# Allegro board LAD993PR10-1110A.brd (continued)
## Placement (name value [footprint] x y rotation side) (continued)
DE8  AZ5125-01H.R7G_SOD523-2  [AZ5125-01HPR7G_SOD523-2]  238.4 31.36 0 top
DE9  -  [RB751S40T1G_SOD523-2]  244.55 38.09 180 top
DH1  -  [RB751S40T1G_SOD523-2]  168.28 20.75 90 top
DI1  -  [RB751S40T1G_SOD523-2]  63.96 27.93 180 top
DI3  AZ5125-02S.R7G_SOT23-3  [AZ5125-02SPR7G_SOT23-3]  62.09 17.9 90 bottom
DI7  -  [AZ1045-04F_DFN2510P10E-10-9]  293.06 53.19 270 bottom
DI8  AZ5125-02S.R7G_SOT23-3  [AZ5125-02SPR7G_SOT23-3]  290.69 56.89 90 bottom
DI9  -  [AZ1045-04F_DFN2510P10E-10-9]  291.91 34.14 270 bottom
DI10  AZ5125-02S.R7G_SOT23-3  [AZ5125-02SPR7G_SOT23-3]  290.18 36.82 90 bottom
DN1  -  [RB751S40T1G_SOD523-2]  197.37 36.38 270 bottom
DN2  -  [RB751S40T1G_SOD523-2]  196.22 36.38 270 bottom
DV1  -  [RB751S40T1G_SOD523-2]  176.47 14.06 180 top
DV2  BAT54CW-7-F_SOT323-3~D  [BAT54CW-7-F_SOT323-3]  65.4 31.46 90 top
DV3  BAT54CW-7-F_SOT323-3~D  [BAT54CW-7-F_SOT323-3]  65.35 33.9 90 top
DV4  -  [AZ1045-04F_DFN2510P10E-10-9]  296.54 78.15 180 top
DV5  -  [AZ1045-04F_DFN2510P10E-10-9]  292.32 66.61 0 top
DV9  -  [RB751S40T1G_SOD523-2]  174.63 71.49 90 bottom
DV11  -  [RB751S40T1G_SOD523-2]  173.75 74.41 90 top
DV12  -  [PESD5V0U2BT_SOT23-3]  233.96 36.91 90 bottom
DV13  -  [BAT54CW-7-F_SOT323-3]  170.19 72.78 90 top
DV14  -  [BAT54CW-7-F_SOT323-3]  150.19 110.53 0 top
DZ1  -  [RB751S40T1G_SOD523-2]  150.39 18.44 0 top
DZ2  -  [RB751S40T1G_SOD523-2]  63.35 63.46 180 top
EC5205  6.8P_0402_50V8C  [C_0402]  240.67 36.77 270 bottom
EC5206  6.8P_0402_50V8C  [C_0402]  241.69 36.77 270 bottom
F1  0.5A_13.2V_NANOSMDC050F-13.2-2  [F_NANOSMDC050F-13P2-2]  122.96 14.32 0 top
FD1  FIDUCAL  [FIDUCIAL_C40M80]  296.58 121.01 180 bottom
FD2  FIDUCIAL  [FIDUCIAL_C40M80]  15.54 13.13 0 top
FD3  FIDUCAL  [FIDUCIAL_C40M80]  6.55 17.16 180 bottom
FD4  FIDUCIAL  [FIDUCIAL_C40M80]  293.28 121.05 0 top
H1  -  [H_3P7]  80.49 108.8 0 top
H2  -  [H_3P7]  139.79 104.55 0 top
H3  -  [H_3P7]  80.49 70.4 0 top
H4  -  [H_3P7]  139.79 71 0 top
H5  -  [H_3P2]  196.29 114.15 0 top
H6  -  [H_3P2]  210.69 68.55 0 top
H10  -  [H_2P8]  85.19 128.9 0 top
H11  -  [H_2P8]  194.09 128.9 0 top
H12  -  [H_2P8]  285.89 107.9 0 top
H13  -  [H_2P5]  304.79 119.2 0 top
H17  -  [H_2P8]  65.29 76.9 0 top
H19  -  [H_2P8]  214.14 53.1 0 top
H20  -  [H_3P3]  40.79 41.75 0 top
H23  -  [H_2P5]  57.49 57.4 0 top
H40  -  [H_2P1N]  301.29 41 0 top
H55  -  [H_2P4X2P1N]  15.29 41 0 top
H56  -  [H_2P5]  88.64 6.97 0 top
H57  -  [H_3P0]  88.64 8.57 0 top
HDA1  ALC3246-CG-GP  [ALC3246-CG_MQFN48_6X6-S]  278.26 26.95 0 top
HT1  100K +-1% 0402 B25/50 4250K  [R_0402]  108.39 85.72 0 top
JADP10  ACES_50290-00701-001  [ACES_50290-00701-001_7P]  8.94 30.4 90 bottom
JAPS  ACES_50506-01841-P01  [ACES_50506-01841-P01_18P]  173.18 11.55 0 top
JBAT10  ACES_50288-01171-001  [ACES_50288-01171-001_11P-T]  45.19 10.84 180 bottom
JBL1  E-T_6913K-Y04N-00L  [E-T_6913K-Y04N-00L_4P]  121.59 15.83 180 bottom
JCAM1  ACES_87212-14G0  [ACES_87212-14G0_14P]  241.02 43.51 0 bottom
JDEG1  ACES_50506-01041-P01  [ACES_50506-01041-P01_10P]  249.22 34.41 0 bottom
JDIMM1  DEREN_40-42271-26001RHF  [DEREN_40-42271-26001RHF_260P-T]  70.65 40.97 0 bottom
JDIMM2  LOTES_ADDR0070-P009A  [LOTES_ADDR0070-P009A_260P-T]  70.66 28.17 180 bottom
JEDP1  ACES_59003-04006-001  [ACES_59003-04006-001_40P]  62.69 24.01 270 bottom
JFAN1  E-T_3806K-F04N-03R  [E-T_3806K-F04N-03R_4P]  56.51 34.65 180 top
JFAN2  E-T_3806K-F04N-03R  [E-T_3806K-F04N-03R_4P]  246.94 34.43 90 top
JHDD1  ACES_50554-01201-001  [ACES_50554-01201-001_12P-T]  195.67 12.21 180 bottom
JHDMI1  ACON_HMR2E-AK120D  [ACON_HMR2E-AK120D_19P]  301.86 78.17 270 bottom
JHP1  SINGA_2SJ3108-007111F  [SINGA_2SJ3108-007111F_6P]  300.84 18.12 90 bottom
JIO1  ACES_88194-3041  [ACES_88194-3041_30P]  9.9 22.75 270 top
JKB1  ACES_50699-03041-P01  [ACES_50699-03041-P01_30P]  196.93 56.91 270 top
JLAN  SANTA_130452-0E1  [SANTA_130452-0E1_8P]  295.47 107.41 270 bottom
JLED  E-T_6915K-Q04N-00L  [E-T_6915K-Q04N-00L_4P]  245.49 24.93 0 top
JLPDE1  ACES_50506-01041-P01  [ACES_50506-01041-P01_10P]  247.02 32.25 180 bottom
JNGFF1  CONCR_213AAAA32FA  [CONCR_213AAAA32FA_67P]  184.31 21.87 0 bottom
JNGFF2  LOTES_APCI0096-P002A  [LOTES_APCI0096-P002A_75P]  208.62 36.83 270 bottom
JPW  ACES_51601-0040M-P01  [ACES_51601-0040M-P01_4P]  201.09 34.57 180 top
JRTC  ACES_50273-0020N-001  [ACES_50273-0020N-001_2P-T]  154.19 13.67 180 bottom
JSPK1  ACES_50224-00601-001  [ACES_50224-00601-001_6P]  300.41 5.88 0 top
JTP  ACES_51524-0080N-001  [ACES_51524-0080N-001_8P]  139.76 15.65 180 bottom
JUART  CVILU_CI1804M1VRA-NH  [CVILU_CI1804M1VRA-NH_4P]  214.21 61.9 90 bottom
JUSB1  LOTES_AUSB0015-P002A  [LOTES_AUSB0015-P002A_9P]  296.41 27.22 270 bottom
JUSB2  LOTES_AUSB0015-P002A  [LOTES_AUSB0015-P002A_9P]  296.41 47.92 270 bottom
LA1  4.7UH +-20% DFE252012F  [TOKO_DFE252012R-H-1R0M_2P]  257.97 12.79 0 bottom
LA2  4.7UH +-20% DFE252012F  [TOKO_DFE252012R-H-1R0M_2P]  261.3 12.79 0 bottom
LA19  BLM15AX700SN1D_2P  [MURAT_BLM15AX700SN1D_2P]  291.51 18.15 0 bottom
LA20  BLM15AX700SN1D_2P  [MURAT_BLM15AX700SN1D_2P]  297.35 15.1 180 top
LA21  BLM15AX700SN1D_2P  [MURAT_BLM15AX700SN1D_2P]  291.7 17.14 0 top
LA22  BLM15AX700SN1D_2P  [MURAT_BLM15AX700SN1D_2P]  297.86 12.94 180 bottom
LA23  BLM15PX181SN1D_2P  [MURAT_BLM15PX181SN1D_2P]  271.02 16.63 180 top
LA24  BLM15PX181SN1D_2P  [MURAT_BLM15PX181SN1D_2P]  272.69 16.63 0 top
LA25  BLM15PX181SN1D_2P  [MURAT_BLM15PX181SN1D_2P]  275.85 16.63 180 top
LA26  BLM15PX181SN1D_2P  [MURAT_BLM15PX181SN1D_2P]  277.64 16.63 0 top
LED3  HT-F196BP5_WHITE  [LED_HT-F196BP5_2P]  286.9 62.72 270 bottom
LED4  HT-F196BP5_WHITE  [LED_HT-F196BP5_2P]  201.44 31.99 0 top
LH1  BLM15PX221SN1D_2P  [MURAT_BLM15PX221SN1D_2P]  172.2 22.54 90 top
LH2  BLM15PX221SN1D_2P  [MURAT_BLM15PX221SN1D_2P]  179.76 27.68 180 top
LI1  MCM1012B900F06BP_4P  [INPAQ_MCM1012B900F06BP_4P]  67.69 17.39 180 bottom
LI2  MCM1012B900F06BP_4P  [INPAQ_MCM1012B900F06BP_4P]  286.91 35.81 0 bottom
LI5  MCM1012B900F06BP_4P  [INPAQ_MCM1012B900F06BP_4P]  288.44 54.86 0 bottom
LN1  MCM1012B900F06BP_4P  [INPAQ_MCM1012B900F06BP_4P]  185.24 18.29 90 bottom
LV7  BLM15AX300SN1D  [C_0402]  160.06 76.6 270 top
LV13  BLM15AX300SN1D  [C_0402]  147.83 102.99 180 bottom
LV22  MCM1012B900F06BP_4P  [INPAQ_MCM1012B900F06BP_4P]  230.65 37.5 0 bottom
LV24  HCM1012GH900BP_4P  [INPAQ_HCM1012GH900BP_4P]  294.02 62.74 90 top
LV25  HCM1012GH900BP_4P  [INPAQ_HCM1012GH900BP_4P]  292.11 62.74 90 top
LV26  HCM1012GH900BP_4P  [INPAQ_HCM1012GH900BP_4P]  296.18 73.41 90 top
LV27  HCM1012GH900BP_4P  [INPAQ_HCM1012GH900BP_4P]  294.27 73.41 90 top
NOREF  -  []  70.23 176.1 0 top
NOREF#2  -  []  40.79 41.75 0 top
NOREF#3  -  []  149.22 176.1 0 top
NOREF#4  -  []  40.93 10.61 0 top
NOREF#5  -  []  137.85 -41.92 0 top
NOREF#6  -  []  84.15 51.29 0 top
NOREF#7  -  []  133.49 8.63 0 top
NOREF#8  -  []  214.14 53.1 0 top
NOREF#9  -  []  285.89 107.9 0 top
NOREF#10  -  []  196.29 114.15 0 top
NOREF#11  -  []  285.79 11.5 0 top
NOREF#12  -  []  57.49 57.4 0 top
NOREF#13  -  []  164.54 6.97 0 top
NOREF#14  -  []  139.79 71 0 top
NOREF#15  -  []  80.49 70.4 0 top
NOREF#16  -  []  85.19 128.9 0 top
NOREF#17  -  []  194.09 128.9 0 top
NOREF#18  -  []  202.79 11.5 0 top
NOREF#19  -  []  210.69 68.55 0 top
NOREF#20  -  []  80.49 108.8 0 top
NOREF#21  -  []  216.57 182.25 0 top
NOREF#22  -  []  304.79 119.2 0 top
NOREF#23  -  []  19.79 7.9 0 top
NOREF#24  -  []  139.79 104.55 0 top
NOREF#25  -  []  65.29 76.9 0 top
NOREF#26  -  []  115.45 8.75 0 top
NOREF#27  -  []  99.04 57.83 0 top
NOREF#28  -  []  124.88 50.21 90 top
NOREF#29  -  []  172.86 110.67 180 bottom
NOREF#30  -  []  81.29 49.77 180 bottom
NOREF#31  -  []  124.93 -17.31 180 bottom
NOREF#32  -  []  107.6 -1.51 180 bottom
NOREF#33  -  []  121.27 49.94 180 bottom
PC100  0.1U_0402_25V6  [C_0402]  12.33 41.01 90 top
PC101  0.1U_0402_25V6  [C_0402]  12.84 39.61 180 top
PC102  0.1U_0402_25V6  [C_0402]  13.92 34.72 270 bottom
PC103  1000P_0402_50V7K  [C_0402]  15.69 34.72 270 bottom
PC104  100P_0402_50V8J  [C_0402]  14.81 34.72 270 bottom
PC105  1000P_0402_50V7K  [C_0402]  16.58 34.72 270 bottom
PC106  100P_0402_50V8J  [C_0402]  16.14 38.47 180 top
PC107  15P_0402_50V8J  [C_0402]  16.16 37.56 180 top
PC108  0.1U_0402_25V6  [C_0402]  14.92 26.28 0 bottom
PC109  100P_0402_50V8J  [C_0402]  39.96 16.88 180 bottom
PC110  0.01UF_0402_25V7K  [C_0402]  39.96 17.77 180 bottom
PC111  1000P_0402_50V7K  [C_0402]  46.92 15.36 0 bottom
PC112  100P_0402_50V8J  [C_0402]  46.92 14.47 0 bottom
PC113  0.22U_0603_25V7K  [C_0603]  207.69 62.22 0 bottom
PC114  0.1U_0402_25V6  [C_0402]  227.97 45.51 90 bottom
PC200  0.1U_0402_25V6  [C_0402]  50.3 42.71 90 bottom
PC202  0.022U_0402_25V7K  [C_0402]  46.24 44.87 90 top
PC203  0.1U_0402_25V6  [C_0402]  50.38 39.87 180 bottom
PC204  0.1U_0402_25V6  [C_0402]  50.4 38.8 180 bottom
PC301  0.1U_0402_25V6  [C_0402]  21.17 33.47 90 top
PC302  0.022U_0603_25V7K  [C_0603]  39.82 18.28 180 top
PC303  2200P_0402_50V7K  [C_0402]  24.11 38.95 0 top
PC304  0.047U_0402_25V7K  [C_0402]  28.71 32.96 270 bottom
PC305  0.1U_0402_25V6  [C_0402]  18.98 26.28 0 bottom
PC306  2200P_0402_50V7K  [C_0402]  18.98 27.42 0 top
PC307  10U_0805_25V6K  [C_0805]  18.72 26.03 0 top
PC308  10U_0805_25V6K  [C_0805]  18.72 24.88 0 bottom
PC309  0.1U_0603_25V7K  [C_0603]  24.27 35.84 0 bottom
PC310  0.1U_0402_25V6  [C_0402]  24.7 34.78 0 bottom
PC311  0.01UF_0402_25V7K  [C_0402]  26.5 34.78 270 bottom
PC312  2.2U_0603_16V6K  [C_0603]  31.12 31.55 90 bottom
PC313  1U_0603_25V6K  [C_0603]  27.57 31.55 90 bottom
PC314  10U_0805_25V5K~D  [C_0805]  43.36 18.15 0 bottom
PC315  680P_0402_50V7K  [C_0402]  23.45 25.64 180 top
PC316  10U_0805_25V5K~D  [C_0805]  43.36 16.25 0 top
PC317  10U_0805_25V5K~D  [C_0805]  43.36 18.02 0 top
PC318  0.1U_0402_25V6  [C_0402]  32.19 35.93 0 top
PC319  0.1U_0402_25V6  [C_0402]  34.05 35.92 90 top
PC320  0.1U_0402_25V6  [C_0402]  33.11 36.82 180 top
PC321  100P_0402_50V8J  [C_0402]  26.93 41.32 90 bottom
PC322  100P_0402_50V8J  [C_0402]  29.6 42.23 270 bottom
PC323  0.01UF_0402_25V7K  [C_0402]  25.99 40.63 180 bottom
PC324  1000P_0402_50V7K  [C_0402]  24.09 37.56 0 top
PC400  4.7U_0603_6.3V6M  [C_0603]  55.57 22.22 0 bottom
PC401  100P_0402_50V8J  [C_0402]  56.27 19.09 90 bottom
PC402  100P_0402_50V8J  [C_0402]  55.69 24.25 0 bottom
PC403  15P_0402_50V8J  [C_0402]  57.92 8.19 270 bottom
PC404  0.1U_0402_25V6  [C_0402]  56.14 8.19 270 bottom
PC405  2200P_0402_50V7K  [C_0402]  47.94 25.39 0 bottom
PC406  2200P_0402_50V7K  [C_0402]  56.32 16.12 0 bottom
PC407  10U_0805_25V6K  [C_0805]  47.42 26.79 0 bottom
PC408  0.1U_0402_25V6  [C_0402]  57.03 8.19 270 bottom
PC409  10U_0805_25V6K  [C_0805]  56.69 14.72 0 bottom
PC410  100U_25V_M  [C_ECST250ADA101MF611]  52.08 13.87 90 bottom
PC411  0.1U_0402_25V6  [C_0402]  52.59 18.23 270 bottom
PC412  0.1U_0402_25V6  [C_0402]  51.83 25.97 270 bottom
PC413  150U_B2_6.3VM_R35M  [C_B2]  78.75 10.64 90 bottom
PC414  150U_B2_6.3VM_R35M  [C_B2]  36.31 31.61 0 bottom
PC415  150U_B2_6.3VM_R35M  [C_B2]  36.33 35.06 270 bottom
PC416  .1U_0402_16V7K  [C_0402]  60.72 9.21 270 bottom
PC417  .1U_0402_16V7K  [C_0402]  50 35.68 180 bottom
PC418  680P_0603_50V7K  [C_0603]  65.86 7.61 180 bottom
PC419  680P_0603_50V7K  [C_0603]  44.9 33.77 0 top
PC420  0.1U_0402_25V6  [C_0402]  49.24 20.44 180 bottom
PC421  4.7U_0603_6.3V6M  [C_0603]  48.5 21.39 90 bottom
PC422  0.1U_0402_25V6  [C_0402]  55.69 26.91 0 bottom
PC423  150U_B2_6.3VM_R35M  [C_B2]  36.31 28.31 0 bottom
PC500  10U_0603_25V6M  [C_0603]  96.4 10.72 90 bottom
PC501  10U_0603_25V6M  [C_0603]  97.67 10.72 90 bottom
PC502  0.1U_0402_25V6  [C_0402]  94.37 10.71 90 bottom
PC503  2200P_0402_25V7K  [C_0402]  95.26 10.71 90 bottom
PC504  680P_0402_50V7K  [C_0402]  109.28 8.02 0 bottom
PC505  .1U_0402_16V7K  [C_0402]  104.48 8.09 0 bottom
PC506  1U_0402_6.3V6K  [C_0402]  103.29 8.42 270 bottom
PC507  2.2U_0402_6.3V6M  [C_0402]  102.4 8.42 270 bottom
PC508  330P_0402_50V7K  [C_0402]  100.57 8.22 180 bottom
PC509  22U_0603_6.3V6M  [C_0603]  107.96 15.14 90 bottom
PC510  22U_0603_6.3V6M  [C_0603]  109.23 15.14 90 bottom
PC511  22U_0603_6.3V6M  [C_0603]  113.07 10.4 270 bottom
PC512  22U_0603_6.3V6M  [C_0603]  111.8 10.4 270 bottom
PC513  22U_0603_6.3V6M  [C_0603]  106.69 15.14 90 bottom
PC514  1U_0402_10V6K  [C_0402]  99.7 14.29 90 bottom
PC515  22U_0603_6.3V6M  [C_0603]  101.46 15.1 90 bottom
PC516  22U_0603_6.3V6M  [C_0603]  102.68 15.1 90 bottom
PC517  0.1U_0402_10V7K  [C_0402]  96.43 13.93 90 bottom
PC518  0.1U_0402_10V7K  [C_0402]  98.74 14.32 90 bottom
PC600  680P_0603_50V7K  [C_0603]  254.84 11.98 180 top
PC601  2200P_0402_50V7K  [C_0402]  249.95 18.53 90 bottom
PC602  0.1U_0402_25V6  [C_0402]  250.83 18.53 90 bottom
PC603  10U_0805_25V6K  [C_0805]  254.52 17.99 270 bottom
PC604  10U_0805_25V6K  [C_0805]  254.52 17.99 270 top
PC605  0.1U_0201_10V6K  [C_0201]  247.91 18.95 270 bottom
PC606  330P_0402_50V7K  [C_0402]  250.94 11.27 90 top
PC607  22U_0603_6.3V6M  [C_0603]  236.86 12.31 270 top
PC608  22U_0603_6.3V6M  [C_0603]  236.86 12.31 270 bottom
PC609  22U_0603_6.3V6M  [C_0603]  236.61 15.55 90 bottom
PC610  22U_0603_6.3V6M  [C_0603]  237.88 14.79 90 top
PC611  2.2U_0402_6.3V6M  [C_0402]  247.91 12.77 270 bottom
PC612  0.1U_0402_25V6  [C_0402]  252.49 12.26 270 bottom
PC613  1U_0402_6.3V6K  [C_0402]  248.85 12.26 270 bottom
PC700  680P_0603_50V7K  [C_0603]  62.71 69.31 90 bottom
PC701  0.1U_0201_10V6K  [C_0201]  70.89 70.22 270 top
PC702  2200P_0402_50V7K  [C_0402]  62.53 71.1 270 top
PC703  10U_0805_25V6K  [C_0805]  67.05 71.07 180 top
PC704  10U_0805_25V6K  [C_0805]  63.88 71.36 270 top
PC705  0.1U_0402_25V6  [C_0402]  61.66 71.1 270 top
PC706  22U_0603_6.3V6M  [C_0603]  72.97 64.89 180 top
PC707  22U_0603_6.3V6M  [C_0603]  72.97 66.16 180 top
PC708  22U_0603_6.3V6M  [C_0603]  72.97 67.43 180 top
PC709  22U_0603_6.3V6M  [C_0603]  72.97 63.62 180 top
PC710  2.2U_0402_6.3V6M  [C_0402]  70.49 66.87 270 top
PC712  330P_0402_50V7K  [C_0402]  67.75 64.13 0 top
PC713  1U_0402_6.3V6K  [C_0402]  69.61 64.07 270 top
PC800  680P_0603_50V7K  [C_0603]  228.74 41.77 90 top
PC801  2200P_0402_50V7K  [C_0402]  224.72 48.63 0 bottom
PC802  0.1U_0402_25V6  [C_0402]  224.72 48.63 0 top
PC803  0.1U_0201_10V6K  [C_0201]  220.86 47.91 270 bottom
PC804  10U_0805_25V6K  [C_0805]  224.33 47.23 0 bottom
PC805  10U_0805_25V6K  [C_0805]  224.33 47.23 0 top
PC806  330P_0402_50V7K  [C_0402]  219.39 40.53 0 bottom
PC807  22U_0603_6.3V6M  [C_0603]  213.56 42.54 0 bottom
PC808  22U_0603_6.3V6M  [C_0603]  213.56 41.27 0 bottom
PC809  22U_0603_6.3V6M  [C_0603]  213.56 42.54 0 top
PC810  22U_0603_6.3V6M  [C_0603]  213.56 41.27 0 top
PC811  2.2U_0402_6.3V6M  [C_0402]  220.3 42.69 180 bottom
PC812  0.1U_0402_25V6  [C_0402]  226.37 38.85 0 bottom
PC813  1U_0402_6.3V6K  [C_0402]  220.3 41.42 180 bottom
PC900  0.1U_0402_25V6  [C_0402]  140.01 122.44 180 bottom
PC901  2200P_0402_50V7K  [C_0402]  140.01 122.44 180 top
PC902  10U_0805_25V6K  [C_0805]  140.55 121.12 180 top
PC903  10U_0805_25V6K  [C_0805]  140.55 121.12 180 bottom
PC904  0.1U_0603_25V7K  [C_0603]  141.95 116.88 180 bottom
PC905  1U_0603_6.3V6M  [C_0603]  138 114.61 270 bottom
PC906  0.1U_0402_16V7K  [C_0402]  141.03 110.1 0 bottom
PC907  10U_0402_6.3V6M  [C_0402]  152.99 124.27 0 bottom
PC908  470U_D2_2VM_R9M  [C_D2]  150.99 120.41 270 bottom
PC909  680P_0402_50V7K  [C_0402]  143.95 132.55 270 top
PC910  470U_D2_2VM_R9M  [C_D2]  146.21 120.41 270 bottom
PC1000  680P_0603_50V7K  [C_0603]  210.58 116.02 90 top
PC1001  0.1U_0201_10V6K  [C_0201]  205.19 121.76 270 bottom
PC1002  10U_0805_25V6K  [C_0805]  210.3 121.22 270 bottom
PC1003  2200P_0402_50V7K  [C_0402]  211.64 120.41 270 bottom
PC1004  0.1U_0402_25V6  [C_0402]  211.64 120.39 270 top
PC1005  10U_0805_25V6K  [C_0805]  210.3 121.22 270 top
PC1006  330P_0402_50V7K  [C_0402]  204.38 115.31 0 bottom
PC1007  22U_0603_6.3V6M  [C_0603]  196.24 120.64 270 bottom
PC1008  22U_0603_6.3V6M  [C_0603]  196.24 121.71 90 top
PC1009  22U_0603_6.3V6M  [C_0603]  196.24 121.71 90 bottom
PC1010  22U_0603_6.3V6M  [C_0603]  196.24 120.63 270 top
PC1011  2.2U_0402_6.3V6M  [C_0402]  204 116.93 90 bottom
PC1012  0.1U_0402_25V6  [C_0402]  209.08 115.28 270 bottom
PC1013  1U_0402_6.3V6K  [C_0402]  208.14 113.5 180 bottom
PC1100  4700P_0402_25V7K  [C_0402]  66.43 83.1 90 bottom
PC1101  0.1U_0402_10V7K  [C_0402]  71.76 80.69 90 bottom
PC1102  1U_0402_16V6K  [C_0402]  71.76 84.01 270 bottom
PC1103  0.22U_0603_25V7K  [C_0603]  73.42 84.38 270 bottom
PC1104  330P_0402_50V7K  [C_0402]  65.67 85.13 90 bottom
PC1105  1000P_0402_50V7K  [C_0402]  65.72 85.97 0 top
PC1106  47P_0402_50V8J  [C_0402]  65.72 86.86 0 top
PC1107  8200P_0402_25V7K  [C_0402]  64.78 86.85 90 top
PC1108  1000P_0402_50V7K  [C_0402]  63.94 88.76 0 bottom
PC1109  680P_0402_50V7K  [C_0402]  64.7 86.92 0 bottom
PC1110  2200P_0402_50V7K  [C_0402]  76.51 87.11 0 bottom
PC1111  .1U_0402_16V7K  [C_0402]  79.44 85.46 0 bottom
PC1112  4700P_0402_16V7K  [C_0402]  79.44 88.13 0 bottom
PC1113  0.033U_0402_16V7K  [C_0402]  79.44 87.24 0 bottom
PC1114  0.01UF_0402_25V7K  [C_0402]  66.63 89.65 180 bottom
PC1115  220P_0402_50V8J  [C_0402]  81.61 92.01 270 bottom
PC1116  0.01UF_0402_25V7K  [C_0402]  76.64 89.14 0 bottom
PC1117  .1U_0402_16V7K  [C_0402]  63.43 90.54 0 bottom
PC1118  0.068U_0402_16V7K  [C_0402]  66.63 90.54 180 bottom
PC1119  2200P_0402_50V7K  [C_0402]  65.72 88.64 0 top
PC1120  330P_0402_50V7K  [C_0402]  76.74 91.71 0 bottom
PC1121  68P_0402_50V8J  [C_0402]  78.55 91.68 0 bottom
PC1122  470P_0402_50V7K  [C_0402]  78.55 90.67 0 bottom
PC1123  2200P_0402_50V7K  [C_0402]  79.46 93.46 180 bottom
PC1124  .1U_0402_16V7K  [C_0402]  64.35 92.32 180 bottom
PC1125  0.022U_0402_25V7K  [C_0402]  74.81 94.78 90 bottom
PC1126  0.022U_0402_25V7K  [C_0402]  65.72 92.32 0 bottom
PC1127  0.022U_0402_25V7K  [C_0402]  73.92 94.78 90 bottom
PC1128  0.022U_0402_25V7K  [C_0402]  73.03 94.78 90 bottom
PC1129  0.022U_0402_25V7K  [C_0402]  65.72 91.43 0 bottom
PC1130  .1U_0402_16V7K  [C_0402]  76.51 98.54 0 bottom
PC1131  .047U_0402_16V7K  [C_0402]  73.03 96.69 90 bottom
PC1132  0.22U_0402_16V7K  [C_0402]  73.92 96.69 90 bottom
PC1133  2200P_0402_50V7K  [C_0402]  77.23 96.69 90 bottom
PC1134  470P_0402_50V7K  [C_0402]  71.51 97.86 270 top
PC1135  0.01UF_0402_25V7K  [C_0402]  71.51 94.78 90 bottom
PC1136  330P_0402_50V7K  [C_0402]  67.95 94.78 90 bottom
PC1137  68P_0402_50V8J  [C_0402]  69.73 95.8 90 top
PC1138  680P_0402_50V7K  [C_0402]  70.62 96.69 90 bottom
PC1139  8200P_0402_25V7K  [C_0402]  69.73 96.69 90 bottom
PC1200  22U_0603_6.3V6M  [C_0603]  121.74 114.16 180 top
PC1201  22U_0603_6.3V6M  [C_0603]  116.91 114.16 0 top
PC1202  22U_0603_6.3V6M  [C_0603]  116.91 112.89 0 top
PC1203  22U_0603_6.3V6M  [C_0603]  108.47 90.35 90 top
PC1204  22U_0603_6.3V6M  [C_0603]  108.47 88.57 270 top
PC1205  22U_0603_6.3V6M  [C_0603]  112.98 114.54 180 top
PC1207  470U_D2_2VM_R4.5M  [C_D2]  115.62 109.24 180 bottom
PC1208  470U_D2_2VM_R4.5M  [C_D2]  120.46 109.31 0 bottom
PC1220  22U_0603_6.3V6M  [C_0603]  119.4 85.51 180 top
PC1221  1U_0402_6.3V6K  [C_0402]  119.34 83.56 180 top
PC1222  1U_0402_6.3V6K  [C_0402]  116.8 85.36 180 top
PC1223  1U_0402_6.3V6K  [C_0402]  116.67 83.22 0 top
PC1224  1U_0402_6.3V6K  [C_0402]  110.3 87.37 0 top
PC1225  1U_0402_6.3V6K  [C_0402]  113.37 87.37 180 top
PC1226  1U_0402_6.3V6K  [C_0402]  110.42 84.95 0 top
PC1229  .1U_0402_16V7K  [C_0402]  113.24 86.22 180 top
PC1230  .1U_0402_16V7K  [C_0402]  113.24 84.95 180 top
PC1231  .1U_0402_16V7K  [C_0402]  118.26 93.76 0 top
PC1232  .1U_0402_16V7K  [C_0402]  110.64 83.16 0 top
PC1233  .1U_0402_16V7K  [C_0402]  119.47 84.45 180 top
PC1239  .1U_0402_16V7K  [C_0402]  109.92 93.51 180 top
PC1240  .1U_0402_16V7K  [C_0402]  118.26 94.65 0 top
PC1241  .1U_0402_16V7K  [C_0402]  110.42 86.22 0 top
PC1242  .1U_0402_16V7K  [C_0402]  110.83 93.53 0 top
PC1243  .1U_0402_16V7K  [C_0402]  116.82 84.45 0 top
PC1244  .1U_0402_16V7K  [C_0402]  110.83 94.42 0 top
PC1245  .1U_0402_16V7K  [C_0402]  113.4 83.16 180 top
PC1246  .1U_0402_16V7K  [C_0402]  108.99 94.42 0 top
PC1247  .1U_0402_16V7K  [C_0402]  120.08 82.44 180 top
PC1248  .1U_0402_16V7K  [C_0402]  115.49 83.29 180 top
PC1261  22U_0603_6.3V6M  [C_0603]  117.04 86.86 180 top
PC1263  22U_0603_6.3V6M  [C_0603]  107.9 114.8 0 top
PC1264  22U_0603_6.3V6M  [C_0603]  107.9 113.53 0 top
PC1265  22U_0603_6.3V6M  [C_0603]  112.98 113.27 180 top
PC1269  22U_0603_6.3V6M  [C_0603]  114.5 84.32 0 top
PC1271  22U_0603_6.3V6M  [C_0603]  114.56 85.52 90 top
PC1274  22U_0603_6.3V6M  [C_0603]  121.74 112.89 180 top
PC1276  22U_0603_6.3V6M  [C_0603]  119.45 86.86 180 top
PC1300  47U_0805_6.3V6M  [C_0805]  102.3 85.95 180 top
PC1301  470U_D2_2VM_R4.5M  [C_D2]  98.96 109.18 0 bottom
PC1303  47U_0805_6.3V6M  [C_0805]  97.56 85.95 0 top
PC1304  47U_0805_6.3V6M  [C_0805]  96.37 85.98 180 top
PC1305  47U_0805_6.3V6M  [C_0805]  96.34 88.18 180 top
PC1306  47U_0805_6.3V6M  [C_0805]  97.75 90.02 0 top
PC1307  470U_D2_2VM_R4.5M  [C_D2]  99.2 114.39 90 bottom
PC1309  47U_0805_6.3V6M  [C_0805]  93.99 107.94 90 bottom
PC1310  47U_0805_6.3V6M  [C_0805]  97.69 88.11 0 top
PC1311  47U_0805_6.3V6M  [C_0805]  96.4 90 180 top
PC1312  47U_0805_6.3V6M  [C_0805]  95.77 107.98 90 bottom
PC1314  22U_0603_6.3V6M  [C_0603]  97.05 91.6 0 top
PC1320  1U_0402_6.3V6K  [C_0402]  107.09 94.35 0 top
PC1321  1U_0402_6.3V6K  [C_0402]  98.77 93.64 0 top
PC1322  1U_0402_6.3V6K  [C_0402]  98.77 92.68 0 top
PC1323  1U_0402_6.3V6K  [C_0402]  105.94 83.17 0 top
PC1324  1U_0402_6.3V6K  [C_0402]  100.86 92.68 0 top
PC1325  1U_0402_6.3V6K  [C_0402]  100.86 93.64 0 top
PC1326  .1U_0402_16V7K  [C_0402]  104.1 83.17 0 top
PC1327  .1U_0402_16V7K  [C_0402]  96.61 93.64 0 top
PC1328  .1U_0402_16V7K  [C_0402]  107.09 93.27 0 top
PC1329  .1U_0402_16V7K  [C_0402]  103.02 93.7 0 top
PC1330  .1U_0402_16V7K  [C_0402]  105.12 92.68 0 top
PC1331  .1U_0402_16V7K  [C_0402]  103.02 92.68 0 top
PC1332  .1U_0402_16V7K  [C_0402]  102.25 83.24 0 top
PC1333  .1U_0402_16V7K  [C_0402]  100.34 83.24 0 top
PC1334  .1U_0402_16V7K  [C_0402]  96.61 92.68 0 top
PC1335  .1U_0402_16V7K  [C_0402]  94.58 92.75 0 top
PC1338  .1U_0402_16V7K  [C_0402]  105.12 93.7 0 top
PC1339  .1U_0402_16V7K  [C_0402]  94.63 83.24 0 top
PC1340  .1U_0402_16V7K  [C_0402]  96.6 83.17 0 top
PC1341  .1U_0402_16V7K  [C_0402]  94.58 93.7 0 top
PC1342  .1U_0402_16V7K  [C_0402]  98.44 83.24 0 top
PC1348  22U_0603_6.3V6M  [C_0603]  102.01 90.26 180 top
PC1349  22U_0603_6.3V6M  [C_0603]  107.14 90.21 180 top
PC1350  22U_0603_6.3V6M  [C_0603]  103.38 86.21 0 top
PC1351  22U_0603_6.3V6M  [C_0603]  107.14 87.53 180 top
PC1352  22U_0603_6.3V6M  [C_0603]  107.14 88.87 180 top
PC1353  22U_0603_6.3V6M  [C_0603]  103.21 87.54 0 top
PC1354  22U_0603_6.3V6M  [C_0603]  103.21 90.27 0 top
PC1359  22U_0603_6.3V6M  [C_0603]  102.02 88.94 180 top
PC1360  22U_0603_6.3V6M  [C_0603]  103.28 88.87 0 top
PC1361  22U_0603_6.3V6M  [C_0603]  101.98 87.55 180 top
PC1362  22U_0603_6.3V6M  [C_0603]  107.14 86.21 180 top
PC1363  22U_0603_6.3V6M  [C_0603]  104.24 84.35 0 top
PC1366  22U_0603_6.3V6M  [C_0603]  100.91 114.16 0 top
PC1367  22U_0603_6.3V6M  [C_0603]  97.74 115.81 0 top
PC1368  22U_0603_6.3V6M  [C_0603]  84.27 116.7 180 top
PC1369  22U_0603_6.3V6M  [C_0603]  97.74 114.54 0 top
PC1370  22U_0603_6.3V6M  [C_0603]  84.27 115.43 180 top
PC1372  22U_0603_6.3V6M  [C_0603]  101.81 84.37 0 top
PC1373  22U_0603_6.3V6M  [C_0603]  99.4 84.37 0 top
PC1374  22U_0603_6.3V6M  [C_0603]  96.99 84.37 0 top
PC1375  22U_0603_6.3V6M  [C_0603]  104.67 91.54 0 top
PC1376  22U_0603_6.3V6M  [C_0603]  103.55 91.6 180 top
PC1377  22U_0603_6.3V6M  [C_0603]  99.59 91.6 0 top
PC1378  22U_0603_6.3V6M  [C_0603]  94.58 84.37 0 top
PC1379  22U_0603_6.3V6M  [C_0603]  96.04 91.63 180 top
PC1380  22U_0603_6.3V6M  [C_0603]  121.87 102.86 180 bottom
PC1382  47U_0805_6.3V6M  [C_0805]  121.88 90.65 180 top
PC1383  .1U_0402_16V7K  [C_0402]  130.26 108.58 180 bottom
PC1384  .1U_0402_16V7K  [C_0402]  135.19 108.58 0 bottom
PC1385  22U_0603_6.3V6M  [C_0603]  121.83 89.13 180 top
PC1386  22U_0603_6.3V6M  [C_0603]  121.65 93.51 180 top
PC1388  47U_0805_6.3V6M  [C_0805]  130.02 112.77 180 bottom
PC1389  22U_0603_6.3V6M  [C_0603]  121.87 104.13 180 bottom
PC1390  22U_0603_6.3V6M  [C_0603]  121.88 87.79 180 top
PC1391  22U_0603_6.3V6M  [C_0603]  134.95 110.99 0 bottom
PC1393  47U_0805_6.3V6M  [C_0805]  129.7 114.25 90 bottom
PC1394  22U_0603_6.3V6M  [C_0603]  134.95 109.72 0 bottom
PC1395  22U_0603_6.3V6M  [C_0603]  130.25 109.72 180 bottom
PC1396  22U_0603_6.3V6M  [C_0603]  130.25 110.99 180 bottom
PC1397  220U_D7_2VM_R6M  [C_EEFSS0D221R]  111.27 90.59 0 top
PC1400  1U_0402_6.3V6K  [C_0402]  120.98 127.45 270 bottom
PC1401  1U_0402_6.3V6K  [C_0402]  124.11 131.84 270 bottom
PC1402  0.22U_0603_16V7K  [C_0603]  125.23 132.26 270 bottom
PC1403  100U_25V_M  [C_ECST250ADA101MF611]  68.71 121.15 180 bottom
PC1404  10U_0805_25V6K  [C_0805]  129.3 127.84 270 top
PC1405  10U_0805_25V6K  [C_0805]  129.3 127.84 270 bottom
PC1406  0.1U_0402_25V6  [C_0402]  127.64 131.1 90 bottom
PC1407  2200P_0402_50V7K  [C_0402]  127.64 131.1 90 top
PC1408  1.5P_0402_50V8C  [C_0402]  128.53 131.1 90 bottom
PC1409  47P_0603_50V8J  [C_0603]  127.39 122.86 90 top
PC1410  1U_0402_6.3V6K  [C_0402]  110.82 127.45 270 bottom
PC1411  1U_0402_6.3V6K  [C_0402]  113.67 132.02 270 bottom
PC1412  0.22U_0603_16V7K  [C_0603]  114.82 132.18 270 bottom
PC1413  10U_0603_25V6M  [C_0603]  119.51 127.82 270 bottom
PC1414  10U_0603_25V6M  [C_0603]  119.51 127.82 270 top
PC1415  0.1U_0402_25V6  [C_0402]  108.47 130.98 90 top
PC1416  2200P_0402_50V7K  [C_0402]  109.36 130.98 90 top
PC1417  47P_0603_50V8J  [C_0603]  116.6 122.74 90 top
PC1418  1U_0402_6.3V6K  [C_0402]  100.91 127.32 270 bottom
PC1419  0.22U_0603_16V7K  [C_0603]  105.17 132.13 270 bottom
PC1420  1U_0402_6.3V6K  [C_0402]  104.02 131.89 270 bottom
PC1421  10U_0805_25V6K  [C_0805]  109.1 127.71 270 bottom
PC1422  10U_0805_25V6K  [C_0805]  109.1 127.71 270 top
PC1423  0.1U_0402_25V6  [C_0402]  107.58 130.98 90 bottom
PC1424  2200P_0402_50V7K  [C_0402]  107.58 130.98 90 top
PC1425  47P_0603_50V8J  [C_0603]  106.69 122.74 90 top
PC1500  1U_0402_6.3V6K  [C_0402]  90.62 127.32 270 bottom
PC1501  1U_0402_6.3V6K  [C_0402]  93.74 131.89 270 bottom
PC1502  0.22U_0603_16V7K  [C_0603]  94.88 132.13 270 bottom
PC1503  10U_0603_25V6M  [C_0603]  98.94 127.71 270 bottom
PC1504  10U_0603_25V6M  [C_0603]  98.94 127.71 270 top
PC1505  0.1U_0402_25V6  [C_0402]  95.73 127.71 270 top
PC1506  2200P_0402_50V7K  [C_0402]  97.29 127.75 270 top
PC1507  680P_0603_50V7K  [C_0603]  96.53 122.74 90 top
PC1508  1U_0402_6.3V6K  [C_0402]  72.4 107.89 270 bottom
PC1509  1U_0402_6.3V6K  [C_0402]  67.37 111.24 0 bottom
PC1510  0.22U_0603_16V7K  [C_0603]  67.13 112.39 0 bottom
PC1511  10U_0805_25V6K  [C_0805]  71.68 116.58 0 top
PC1512  10U_0805_25V6K  [C_0805]  71.68 116.58 0 bottom
PC1513  0.1U_0402_25V6  [C_0402]  68.54 114.8 180 bottom
PC1514  2200P_0402_50V7K  [C_0402]  68.54 114.8 180 top
PC1515  680P_0603_50V7K  [C_0603]  78.56 117.47 180 top
PC1516  2200P_0402_50V7K  [C_0402]  136.03 125.97 270 top
PC1517  0.1U_0402_25V6  [C_0402]  138.82 125.97 270 top
PC1518  10U_0805_25V6K  [C_0805]  137.42 126.48 270 bottom
PC1519  10U_0805_25V6K  [C_0805]  137.42 126.48 270 top
PC1520  4.7U_0402_6.3V6M  [C_0402]  132.85 130.17 270 bottom
PC1521  680P_0603_50V7K  [C_0603]  136.08 121.97 90 top
PC1522  0.22U_0603_16V7K  [C_0603]  133.99 130.42 270 bottom
PC1523  4.7U_0402_6.3V6M  [C_0402]  130.69 126.23 270 bottom
PC1600  0.1U_0402_25V6  [C_0402]  178.83 54.22 0 bottom
PC1601  10U_0805_25V6K  [C_0805]  168.81 49.85 180 bottom
PC1602  10U_0805_25V6K  [C_0805]  154.5 49.52 0 bottom
PC1603  47P_0402_50V8J  [C_0402]  163.18 48.47 90 bottom
PC1604  0.1U_0402_25V6  [C_0402]  161.22 48.43 90 bottom
PC1605  2200P_0402_50V7K  [C_0402]  165.13 48.52 90 bottom
PC1606  100U_25V_M  [C_ECST250ADA101MF611]  147.48 43.14 90 bottom
PC1608  .01U_0402_16V7K  [C_0402]  178.8 55.51 0 bottom
PC1609  4.7U_0603_6.3V6K  [C_0603]  173.19 88.66 90 top
PC1610  4.7U_0603_6.3V6K  [C_0603]  148.85 64.32 270 top
PC1611  4.7U_0603_6.3V6K  [C_0603]  144.73 64.13 180 bottom
PC1612  4.7U_0603_6.3V6K  [C_0603]  144.73 65.4 180 bottom
PC1613  4.7U_0603_6.3V6K  [C_0603]  166.94 82.4 180 top
PC1614  4.7U_0603_6.3V6K  [C_0603]  164.17 84 0 top
PC1615  4.7U_0603_6.3V6K  [C_0603]  167.39 93.11 90 top
PC1616  4.7U_0603_6.3V6K  [C_0603]  169.39 93.11 90 top
PC1617  4.7U_0603_6.3V6K  [C_0603]  171.39 89.61 90 top
PC1618  4.7U_0603_6.3V6K  [C_0603]  167.69 85.73 0 top
PC1619  4.7U_0603_6.3V6K  [C_0603]  170.82 82.71 90 top
PC1620  4.7U_0603_6.3V6K  [C_0603]  165.39 91.01 270 top
PC1621  4.7U_0603_6.3V6K  [C_0603]  165.54 87 270 top
PC1622  4.7U_0603_6.3V6K  [C_0603]  144.73 66.67 180 bottom
PC1623  4.7U_0603_6.3V6K  [C_0603]  144.73 67.94 180 bottom
PC1624  4.7U_0603_6.3V6K  [C_0603]  164.35 64.32 270 top
PC1625  4700P_0402_50V7K  [C_0402]  179.74 57.29 180 top
PC1626  0.22U_0603_25V7K  [C_0603]  172.24 59.34 270 bottom
PC1627  470U_D2_2VM_R4.5M  [C_D2]  171.11 68.81 270 bottom
PC1628  470U_D2_2VM_R4.5M  [C_D2]  161.1 68.8 0 top
PC1629  470U_D2_2VM_R4.5M  [C_D2]  154.59 68.62 180 top
PC1630  47P_0603_50V8J  [C_0603]  161.3 58.26 270 top
PC1631  4.7U_0603_6.3V6K  [C_0603]  167.99 81.36 0 top
PC1632  4.7U_0603_6.3V6K  [C_0603]  167.99 79.76 0 top
PC1633  4.7U_0603_6.3V6K  [C_0603]  167.99 78.13 0 top
PC1634  4.7U_0603_6.3V6K  [C_0603]  166.76 81.14 270 top
PC1635  4.7U_0603_6.3V6K  [C_0603]  166.74 78.79 270 top
PC1636  4.7U_0603_6.3V6K  [C_0603]  168.16 74.16 0 top
PC1637  22U_0603_6.3V6M  [C_0603]  153.76 75.24 180 top
PC1638  22U_0603_6.3V6M  [C_0603]  169.09 91.61 180 top
PC1639  22U_0603_6.3V6M  [C_0603]  164.54 72 180 top
PC1640  22U_0603_6.3V6M  [C_0603]  173.19 83.11 90 top
PC1641  22U_0603_6.3V6M  [C_0603]  147.58 64.32 270 top
PC1642  22U_0603_6.3V6M  [C_0603]  163.08 64.32 270 top
PC1643  22U_0603_6.3V6M  [C_0603]  161.81 64.32 270 top
PC1644  1U_0402_16V6K  [C_0402]  171.71 54.22 180 top
PC1645  0.1U_0402_25V6  [C_0402]  178.83 54.22 0 top
PC1646  0.22U_0603_25V7K  [C_0603]  172.24 51.93 270 bottom
PC1647  22U_0603_6.3V6M  [C_0603]  160.54 64.32 270 top
PC1648  22U_0603_6.3V6M  [C_0603]  159.27 64.32 270 top
PC1649  22U_0603_6.3V6M  [C_0603]  156.73 64.32 270 top
PC1650  22U_0603_6.3V6M  [C_0603]  155.46 64.32 270 top
PC1651  22U_0603_6.3V6M  [C_0603]  158 64.32 270 top
PC1652  22U_0603_6.3V6M  [C_0603]  154.19 64.32 270 top
PC1653  22U_0603_6.3V6M  [C_0603]  152.92 64.34 270 top
PC1654  10U_0805_25V6K  [C_0805]  152.08 45.58 0 bottom
PC1655  47P_0402_50V8J  [C_0402]  164.18 48.47 90 bottom
PC1656  1U_0402_6.3V6K  [C_0402]  163.89 88.35 90 top
PC1657  1U_0402_6.3V6K  [C_0402]  165.66 78.23 270 top
PC1658  1U_0402_6.3V6K  [C_0402]  167.01 88.2 270 top
PC1659  1U_0402_6.3V6K  [C_0402]  168.85 90.31 180 top
PC1660  1U_0402_6.3V6K  [C_0402]  163.99 94.27 270 top
PC1661  1U_0402_6.3V6K  [C_0402]  172.89 94.27 270 top
PC1662  10U_0805_25V6K  [C_0805]  159.85 48.08 90 bottom
PC1663  0.1U_0402_25V6  [C_0402]  162.21 48.45 90 bottom
PC1664  2200P_0402_50V7K  [C_0402]  166.06 48.5 90 bottom
PC1665  1U_0402_6.3V6K  [C_0402]  167.93 84.31 0 top
PC1666  1U_0402_6.3V6K  [C_0402]  168.38 82.41 0 top
PC1667  1U_0402_6.3V6K  [C_0402]  170.98 88.33 0 top
PC1668  1U_0402_6.3V6K  [C_0402]  171.89 83.35 90 top
PC1669  10U_0603_6.3V6M  [C_0603]  150.12 64.32 270 top
PC1670  10U_0603_6.3V6M  [C_0603]  151.65 64.32 270 top
PC1671  10U_0603_6.3V6M  [C_0603]  158.76 71.81 90 top
PC1672  10U_0603_6.3V6M  [C_0603]  169.43 64.32 270 top
PC1673  10U_0603_6.3V6M  [C_0603]  168.16 64.32 270 top
PC1674  10U_0603_6.3V6M  [C_0603]  166.89 64.32 270 top
PC1675  10U_0603_6.3V6M  [C_0603]  165.62 64.32 270 top
PC1676  100P_0402_50V8J  [C_0402]  179.6 51.35 180 bottom
PC1677  0.01U_0402_16V7K  [C_0402]  176.55 51.79 270 bottom
PC1678  47P_0603_50V8J  [C_0603]  142.66 57.95 270 top
PC1700  0.1U_0402_25V6  [C_0402]  206.61 48.91 270 top
PC1701  10U_0603_25V6M  [C_0603]  202.75 61.48 270 bottom
PC1702  10U_0603_25V6M  [C_0603]  197.46 61.46 270 bottom
PC1703  47P_0402_50V8J  [C_0402]  203.89 61.03 270 bottom
PC1704  0.1U_0402_25V6  [C_0402]  196.24 61.03 270 bottom
PC1705  2200P_0402_50V7K  [C_0402]  195.28 61.05 270 bottom
PC1707  .01U_0402_16V7K  [C_0402]  204.33 48.86 0 top
PC1708  470U_D2_2VM_R4.5M  [C_D2]  181.47 69.99 0 top
PC1709  4700P_0402_50V7K  [C_0402]  204.33 47.97 0 top
PC1710  0.22U_0603_25V7K  [C_0603]  203.58 57.42 270 top
PC1711  47P_0603_50V8J  [C_0603]  192.81 70.98 0 top
PC1712  1U_0402_16V6K  [C_0402]  205.52 56.17 90 top
PC1713  0.1U_0402_25V6  [C_0402]  209.28 47.36 0 top
PC1714  4.7U_0603_6.3V6K  [C_0603]  184.54 61.52 270 bottom
PC1715  4.7U_0603_6.3V6K  [C_0603]  186.89 65.78 0 top
PC1716  4.7U_0603_6.3V6K  [C_0603]  164.22 87.02 270 top
PC1717  4.7U_0603_6.3V6K  [C_0603]  182 61.52 270 top
PC1718  4.7U_0603_6.3V6K  [C_0603]  165.39 94.01 270 top
PC1719  4.7U_0603_6.3V6K  [C_0603]  185.81 61.52 270 bottom
PC1720  22U_0603_6.3V6M  [C_0603]  185.81 61.52 270 top
PC1721  22U_0603_6.3V6M  [C_0603]  184.54 61.52 270 top
PC1722  22U_0603_6.3V6M  [C_0603]  183.27 61.52 270 top
PC1723  100P_0402_50V8J  [C_0402]  208.42 50.71 90 top
PC1724  1U_0402_6.3V6K  [C_0402]  171.46 94.22 270 top
PC1725  1U_0402_6.3V6K  [C_0402]  172.91 92.29 270 top
PC1726  1U_0402_6.3V6K  [C_0402]  172.93 87.29 270 top
PC1727  10U_0603_6.3V6M  [C_0603]  186.89 64.51 0 top
PC1728  10U_0603_6.3V6M  [C_0603]  186.89 67.05 0 top
PC1729  10U_0603_6.3V6M  [C_0603]  180.73 61.52 270 top
PC1730  1U_0402_6.3V6K  [C_0402]  163.99 92.32 270 top
PC1731  0.01U_0402_16V7K  [C_0402]  208.44 52.97 0 top
PC1732  1U_0402_6.3V6K  [C_0402]  171.59 92.45 180 top
PC1733  4.7U_0603_6.3V6K  [C_0603]  187.08 61.52 270 top
PC1734  4.7U_0603_6.3V6K  [C_0603]  183.27 61.52 270 bottom
PC1735  4.7U_0603_6.3V6K  [C_0603]  182 61.52 270 bottom
PC1736  4.7U_0603_6.3V6K  [C_0603]  180.73 61.52 270 bottom
PC1737  4.7U_0603_6.3V6K  [C_0603]  186.89 63.24 0 top
PC1738  4.7U_0603_6.3V6K  [C_0603]  169.3 89.08 270 top
PC1739  4.7U_0603_6.3V6K  [C_0603]  171.39 85.61 90 top
PC1800  0.1U_0402_16V7K  [C_0402]  146.24 17.2 0 bottom
PC1801  22U_0603_6.3V6M  [C_0603]  144.45 17.03 270 bottom
PC1802  22P_0402_50V8J  [C_0402]  146.14 25.83 0 bottom
PC1803  22U_0603_6.3V6M  [C_0603]  144.8 25.96 180 bottom
PC1804  1U_0402_6.3V6K  [C_0402]  143.37 17.08 270 bottom
PD100  AZ5125-01H.R7G_SOD523-2  [AZ5125-01HPR7G_SOD523-2]  15.24 33.14 180 top
PD101  -  [TVNST52302AB0_SOT523-3]  22.55 14.09 90 bottom
PD102  -  [TVNST52302AB0_SOT523-3]  25.41 16.57 180 bottom
PD300  BAT54CW-7-F SOT-323  [BAT54CW_SOT323-3]  24.17 33.7 90 top
PD401  -  [TVNST52302AB0_SOT523-3]  53.1 28.76 180 bottom
PH1100  470K_0402_5%_ TSM0B474J4702RE  [R_0402]  98.43 122.72 90 bottom
PH1101  10K_0402_5%_B25/50 4250K  [R_0402]  130.69 117.26 90 bottom
PH1102  10K_0402_5%_B25/50 4250K  [R_0402]  87.77 120.44 90 bottom
PH1103  10K_0402_5%_B25/50 4250K  [R_0402]  119.77 113.58 90 bottom
PH1104  470K_0402_5%_ TSM0B474J4702RE  [R_0402]  128.03 122.75 270 bottom
PJ600  -  [JUMP_43X79]  254.9 22.64 270 bottom
PJ601  -  [JUMP_43X118]  234.34 13.2 180 bottom
PJ700  JUMP_43X79  [JUMP_43X79-NPM]  71.39 74.93 225 top
PJ701  -  [JUMP_43X118]  72.65 61.37 270 top
PJ800  -  [JUMP_43X79]  221.46 48.63 0 top
PJ801  -  [JUMP_43X118]  211.63 43.17 180 bottom
PJ1000  -  [JUMP_43X79]  194.52 121.4 180 bottom
PJ1001  -  [JUMP_43X79]  207.15 122.77 0 top
PJP15  PAD-OPEN 43x39  [JUMP_43X39]  211.34 15.48 180 top
PJP35  JUMP_43X39  [JUMP_43X39-NPM]  65.94 41.39 180 top
PJP36  JUMP_43X39  [JUMP_43X39-NPM]  218.69 38.98 180 bottom
PJP70  JUMP_43X39  [JUMP_43X39-NPM]  148.64 28.23 180 top
PJP300  -  [JUMP_43X79]  20.37 23.23 180 top
PJP400  -  [JUMP_43X118]  44.04 21.71 0 bottom
PJP401  PAD-OPEN 4x4m  [JUMP_43X118]  78.88 13.54 90 bottom
PJP402  PAD-OPEN 4x4m  [JUMP_43X118]  37.47 32.93 270 top
PJP500  -  [JUMP_43X118]  112.56 14.53 90 bottom
PJP501  -  [JUMP_43X39]  104.11 15.87 0 bottom
PJP900  PAD-OPEN 3x3m  [JUMP_43X79]  139.86 118.28 180 top
PJP901  PAD-OPEN 4x4m  [JUMP_43X118]  150.23 119.22 0 top
PJP902  PAD-OPEN 4x4m  [JUMP_43X118]  145.7 117.89 270 top
PJP1302  PAD-OPEN 43x39  [JUMP_43X39]  171.66 39.41 270 top
PJP1303  PAD-OPEN 43x39  [JUMP_43X39]  178.65 37.2 180 top
PJP1304  -  [JUMP_43X39]  152.68 16.11 90 bottom
PJP1400  -  [JUMP_43X118]  120.28 132.37 270 top
PJP1500  -  [JUMP_43X118]  66.81 120.17 270 top
PJP1501  -  [JUMP_43X118]  135.9 132.2 270 top
PL100  HCB2012KF-121T50_0805  [TAI-T_HCB2012KF-121T50_2P]  14.38 36.03 0 bottom
PL101  HCB2012KF-121T50_0805  [TAI-T_HCB2012KF-121T50_2P]  14.38 37.68 0 bottom
PL102  HCB2012KF-121T50_0805  [TAI-T_HCB2012KF-121T50_2P]  14.38 32.5 0 bottom
PL103  HCB2012KF-121T50_0805  [TAI-T_HCB2012KF-121T50_2P]  14.38 30.85 0 bottom
PL104  HCB2012KF-121T50_0805  [TAI-T_HCB2012KF-121T50_2P]  14.38 29.2 0 bottom
PL105  HCB2012KF-121T50_0805  [TAI-T_HCB2012KF-121T50_2P]  14.38 27.55 0 bottom
PL106  BLM15AG102SN1D_2P  [MURAT_BLM15AG102SN1D_2P]  14.91 32.12 180 top
PL107  HCB2012KF-121T50_0805  [TAI-T_HCB2012KF-121T50_2P]  43.46 14.72 0 bottom
PL108  HCB2012KF-121T50_0805  [TAI-T_HCB2012KF-121T50_2P]  43.46 16.37 0 bottom
PL300  HCB2012KF-121T50_0805  [TAI-T_HCB2012KF-121T50_2P]  20.82 20.44 180 top
PL301  HCB2012KF-121T50_0805  [TAI-T_HCB2012KF-121T50_2P]  20.82 18.79 180 top
PL302  5.6UH_PCMB104T-5R6MS_8A_20%  [CYNTE_PCMB104T-5R6MS_2P]  28.68 21.07 0 bottom
PL400  HCB2012KF-121T50_0805  [TAI-T_HCB2012KF-121T50_2P]  43.59 26.91 0 bottom
PL401  HCB2012KF-121T50_0805  [TAI-T_HCB2012KF-121T50_2P]  43.59 25.26 0 bottom
PL402  3.3UH_PCMB063T-3R3MS_6.5A_20%  [CYNTE_PCMB063T-3R3MS_2P]  74.28 11.93 180 bottom
PL403  1.5UH_PCMC063T-1R5MN_9A_20%  [CYNTE_PCMC063T-1R5MN_2P]  41.67 29.96 90 bottom
PL500  HCB2012KF-121T50_0805  [TAI-T_HCB2012KF-121T50_2P]  94.73 7.58 90 bottom
PL501  1UH_PCMB053T-1R0MS_7A_20%  [CYNTE_PCMB053T-1R0MS_2P]  104.82 11.22 0 bottom
PL600  HCB2012KF-121T50_0805  [TAI-T_HCB2012KF-121T50_2P]  252.1 22.58 270 bottom
PL601  1UH_PCMB063T-1R0MS_12A_20%  [CYNTE_PCMB063T-1R0MS_2P]  245.5 14.47 180 bottom
PL700  HCB2012KF-121T50_0805  [TAI-T_HCB2012KF-121T50_2P]  71.71 75.25 225 top
PL701  1UH_PCMB053T-1R0MS_7A_20%  [CYNTE_PCMB053T-1R0MS_2P]  70.98 71.75 0 bottom
PL800  HCB2012KF-121T50_0805  [TAI-T_HCB2012KF-121T50_2P]  220.12 49.08 0 bottom
PL801  1UH_PCMB053T-1R0MS_7A_20%  [CYNTE_PCMB053T-1R0MS_2P]  219.2 45.8 180 bottom
PL900  HCB2012KF-121T50_0805  [TAI-T_HCB2012KF-121T50_2P]  141.08 119.42 180 bottom
PL901  0.82UH_MMD-06CZ-R82M-V1L_13A_20%  [MAG_MMD-06CZ-R82M-V1L_2P]  147.79 130.09 270 bottom
PL1000  HCB2012KF-121T50_0805  [TAI-T_HCB2012KF-121T50_2P]  206.74 123.66 0 bottom
PL1001  1UH_PCMB053T-1R0MS_7A_20%  [CYNTE_PCMB053T-1R0MS_2P]  203.4 121.48 180 bottom
PL1400  HCB2012KF-121T50_0805  [TAI-T_HCB2012KF-121T50_2P]  120.15 132.94 270 bottom
PL1401  HCB2012KF-121T50_0805  [TAI-T_HCB2012KF-121T50_2P]  117.61 132.94 270 bottom
PL1402  0.22UH_PCME064T-R22MS0R985_28A_20%  [CYNTE_PCME064T-R22MS0R985_2P]  123.76 121.08 270 bottom
PL1403  0.22UH_PCME064T-R22MS0R985_28A_20%  [CYNTE_PCME064T-R22MS0R985_2P]  114.87 121.13 270 bottom
PL1404  0.22UH_PCME064T-R22MS0R985_28A_20%  [CYNTE_PCME064T-R22MS0R985_2P]  105.22 120.96 270 bottom
PL1500  HCB2012KF-121T50_0805  [TAI-T_HCB2012KF-121T50_2P]  67.07 119.38 270 bottom
PL1501  HCB2012KF-121T50_0805  [TAI-T_HCB2012KF-121T50_2P]  65.11 119.38 270 bottom
PL1502  0.22UH_PCME064T-R22MS0R985_28A_20%  [CYNTE_PCME064T-R22MS0R985_2P]  91.76 121 270 bottom
PL1503  0.22UH_PCME064T-R22MS0R985_28A_20%  [CYNTE_PCME064T-R22MS0R985_2P]  79.15 116.96 0 bottom
PL1504  HCB2012KF-121T50_0805  [TAI-T_HCB2012KF-121T50_2P]  137.17 132.2 270 bottom
PL1505  0.47UH_MMD05CZR47M_12A_20%  [MAG_MMD05CZR47M_4P]  134.12 119.88 270 bottom
PL1600  HCB2012KF-121T50_0805  [TAI-T_HCB2012KF-121T50_2P]  153.56 42.72 270 bottom
PL1601  HCB2012KF-121T50_0805  [TAI-T_HCB2012KF-121T50_2P]  151.82 42.72 270 bottom
PL1602  0.22UH_MMD-10DZ-R22MEX2L_35A_20%  [MAG_MMD-10DZ-R22MEX2L_2P]  163.46 59.58 90 bottom
PL1603  0.22UH_MMD-10DZ-R22MEX2L_35A_20%  [MAG_MMD-10DZ-R22MEX2L_2P]  152.56 59.63 90 bottom
PL1700  HCB2012KF-121T50_0805  [TAI-T_HCB2012KF-121T50_2P]  201.15 61.03 270 bottom
PL1701  HCB2012KF-121T50_0805  [TAI-T_HCB2012KF-121T50_2P]  199.39 61.05 270 bottom
PL1702  0.22UH_MMD-10DZ-R22MEX2L_35A_20%  [MAG_MMD-10DZ-R22MEX2L_2P]  192.16 67.35 180 bottom
PQ100  -  [FDV301N-G_SOT23-3]  14.36 30.37 180 top
PQ101  -  [MMBT3904WH_SOT323-3]  14.4 24.76 270 top
PQ102  -  [AON7409_DFN8-5]  208.15 58.74 90 bottom
PQ103  2N7002EDW_SOT363-6  [2N7002DW-7-F_SOT363-6]  211.17 64.01 0 bottom
PQ200  2N7002EDW_SOT363-6  [2N7002DW-7-F_SOT363-6]  49.22 44.2 270 bottom
PQ201  L2N7002WT1G 1N SC-70-3  [SSM3K7002FU_SC70-3]  46.1 45.5 180 bottom
PQ202  L2N7002WT1G 1N SC-70-3  [SSM3K7002FU_SC70-3]  48.64 47.65 0 bottom
PQ203  2N7002EDW_SOT363-6  [2N7002DW-7-F_SOT363-6]  46.35 38.08 90 bottom
PQ300  L2N7002WT1G 1N SC-70-3  [SSM3K7002FU_SC70-3]  19.52 34.15 180 top
PQ301  -  [AON6426_DFN5X6-8-5]  22.49 36.39 180 bottom
PQ302  -  [AON6426_DFN5X6-8-5]  18.3 34.21 0 bottom
PQ303  -  [AON6426_DFN5X6-8-5]  35.57 19.93 0 top
PQ304  -  [AON6428L_DFN8-5]  25.16 22.72 270 bottom
PQ305  -  [AON7518_DFN8-5]  22.54 24.92 90 bottom
PQ306  -  [AON6426_DFN5X6-8-5]  18.68 36.31 0 top
PQ400  -  [AON7408L_DFN8-5]  59.78 12.9 270 bottom
PQ401  -  [AON6992_DFN5X6D-8-7]  49.92 28.57 180 bottom
PQ402  -  [AON7506_DFN33-8-5]  63.48 10.37 180 bottom
PQ403  -  [L2N7002WT1G_SC70-3]  55.38 28 180 bottom
PQ900  -  [AON6992_DFN5X6D-8-7]  143.32 123.84 180 bottom
PQ901  PJC138K 1N SOT-323-3  [RJU003N03_UMT3]  144.08 111.32 90 top
PQ1600  -  [AON6992_DFN5X6D-8-7]  154.67 51.63 90 bottom
PQ1601  -  [AON6992_DFN5X6D-8-7]  168.44 55.46 270 bottom
PQ1602  -  [AON6992_DFN5X6D-8-7]  150.28 55.87 270 bottom
PQ1603  -  [AON6992_DFN5X6D-8-7]  150.3 49.77 270 bottom
PQ1700  -  [AON6992_DFN5X6D-8-7]  205.61 63.23 180 bottom
PQ1701  -  [AON6992_DFN5X6D-8-7]  199.67 63.21 180 bottom
PR100  0_0402_5%  [R_0402]  16.77 30.17 270 top
PR101  2.2K_0402_1%  [R_0402]  15.81 26.53 0 top
PR102  0_0402_5%  [R0402_0OHM]  16.77 28.39 270 top
PR103  100K_0402_1%  [R_0402]  12.53 26.53 180 top
PR104  10K_0402_1%  [R_0402]  13.4 26.53 0 top
PR105  15K_0402_1%  [R_0402]  11.69 25.59 270 top
PR106  1M_0402_5%  [R_0402]  207.99 63.29 0 bottom
PR107  680K_0402_1%  [R_0402]  210.02 62.93 270 bottom
PR108  100_0402_1%  [R_0402]  23.5 14.26 270 bottom
PR109  100_0402_1%  [R_0402]  24.39 14.26 270 bottom
PR110  100K_0402_1%  [R_0402]  213.47 63.21 90 bottom
PR111  100_0402_1%  [R_0402]  26.25 13.33 180 bottom
PR112  10K_0402_1%  [R_0402]  25.33 14.21 0 bottom
PR113  0_0402_5%  [R0402_0OHM]  208.06 56.96 0 bottom
PR114  33_0402_5%  [R_0402]  14.03 34.15 0 top
PR115  1M_0402_1%  [R_0402]  210.73 56.96 180 bottom
PR200  10K_0402_1%  [R_0402]  35.06 42.23 270 bottom
PR201  6.49K_0402_1%  [R_0402]  34.17 41.32 90 bottom
PR202  10K_0402_5%  [R_0402]  49.46 41.77 0 bottom
PR203  1M_0402_1%  [R_0402]  47.25 41.77 0 bottom
PR204  100K_0402_1%  [R_0402]  51.31 44.36 270 bottom
PR205  10K_0402_1%  [R_0402]  47.14 42.15 180 top
PR206  160K_0402_1%  [R_0402]  46.24 43.09 90 top
PR207  12.4K_0402_1%  [R_0402]  47.13 43.09 90 top
PR208  10K_0402_1%  [R_0402]  49.46 40.76 0 bottom
PR209  1M_0402_1%  [R_0402]  46.38 40.76 180 bottom
PR210  3.3K_0402_1%  [R_0402]  47.25 40.76 0 bottom
PR211  100K_0402_1%  [R_0402]  50.3 47.18 270 bottom
PR212  200K_0402_1%  [R_0402]  50.39 37.87 180 bottom
PR213  1M_0402_1%  [R_0402]  46.24 43.5 270 bottom
PR214  1M_0402_1%  [R_0402]  45.35 38.8 270 bottom
PR215  0_0402_5%  [R0402_0OHM]  44.03 47.23 180 bottom
PR216  0_0402_5%  [R0402_0OHM]  44.03 46.22 180 bottom
PR217  0_0402_5%  [R0402_0OHM]  48.6 48.89 180 bottom
PR300  3M_0402_5%  [R_0402]  21.17 32.63 270 top
PR301  1M_0402_1%  [R_0402]  22.06 31.71 90 top
PR302  0.01_1206_1%  [R_1206_4P-D]  24.44 29.39 0 bottom
PR303  4.7_0402_5%  [R_0402]  17.69 34.48 0 top
PR304  0_0402_5%  [R0402_0OHM]  24.71 32.98 90 bottom
PR305  0_0402_5%  [R0402_0OHM]  25.6 32.98 90 bottom
PR306  10K_0402_1%  [R_0402]  39.63 17.21 270 top
PR307  10_0402_1%  [R_0402]  38.62 17.21 270 top
PR308  4.12K_0603_1%  [R_0603]  24.75 35.6 0 top
PR309  4.12K_0603_1%  [R_0603]  24.27 37.07 0 bottom
PR310  10_1206_1%  [R_1206]  23.53 30.9 0 top
PR311  2.2_0603_5%  [R_0603]  29.85 31.55 90 bottom
PR312  20K_0402_1%  [R_0402]  34.17 34.08 90 bottom
PR313  8.2K_0402_1%  [R_0402]  33.28 34.99 270 bottom
PR314  0.01_1206_1%  [R_1206_4P-D]  41.6 21.02 270 bottom
PR315  4.7_1206_5%  [R_1206]  24.9 23.04 90 top
PR316  100K_0402_1%  [R_0402]  24.95 39.36 0 bottom
PR317  324K_0402_1%  [R_0402]  25.08 41.52 0 bottom
PR318  120K_0402_5%  [R_0402]  25.87 38.47 180 bottom
PR319  0_0402_5%  [R0402_0OHM]  27.82 42.23 270 bottom
PR320  10K_0402_1%  [R_0402]  33.33 38.98 0 bottom
PR321  0_0402_5%  [R0402_0OHM]  35.95 41.32 90 bottom
PR322  10_0402_1%  [R_0402]  33.21 35.93 0 bottom
PR323  52.3K_0402_1%  [R_0402]  25.99 42.41 180 bottom
PR324  10_0402_1%  [R_0402]  33.21 36.82 0 bottom
PR325  4.7_0402_5%  [R_0402]  24.09 36.67 0 top
PR326  0_0402_5%  [R_0402]  31.51 41.32 90 bottom
PR327  0_0402_5%  [R0402_0OHM]  32.39 41.32 90 bottom
PR328  0_0402_5%  [R0402_0OHM]  33.28 41.32 90 bottom
PR329  0_0402_5%  [R_0402]  30.49 41.32 90 bottom
PR400  0_0402_5%  [R0402_0OHM]  56.6 21.07 180 bottom
PR401  68.1K_0402_1%  [R_0402]  57.16 19.09 90 bottom
PR402  154K_0402_1%  [R_0402]  55.69 25.14 0 bottom
PR403  100K_0402_1%  [R_0402]  58.05 19.09 90 bottom
PR404  100K_0402_1%  [R_0402]  55.69 23.36 0 bottom
PR405  22K_0402_1%  [R_0402]  55.38 17.69 90 bottom
PR406  4.75K_0402_1%  [R_0402]  54.49 25.06 90 bottom
PR407  0_0402_5%  [R0402_0OHM]  54.49 17.69 90 bottom
PR408  0_0402_5%  [R0402_0OHM]  57.24 17.26 180 bottom
PR409  0_0402_5%  [R0402_0OHM]  53.6 25.06 90 bottom
PR410  100K_0402_1%  [R_0402]  57.24 18.15 180 bottom
PR411  200_0402_1%  [R_0402]  52.71 25.06 90 bottom
PR412  2.2_0603_5%  [R_0603]  51.44 16.82 90 bottom
PR413  2.2_0603_5%  [R_0603]  50.68 24.82 90 bottom
PR414  4.7_1206_5%  [R_1206]  65.34 11.55 270 bottom
PR415  4.7_1206_5%  [R_1206]  46.94 32.12 180 top
PR416  0_0402_5%  [R0402_0OHM]  49.16 18.58 90 bottom
PR418  2.2K_0402_5%  [R_0402]  56.6 26.03 180 bottom
PR419  0_0402_5%  [R0402_0OHM]  56.02 32.07 270 bottom
PR500  100K_0402_5%  [R_0402]  96 8.37 270 bottom
PR501  100K_0402_5%  [R_0402]  96.89 8.37 270 bottom
PR502  4.7_0805_5%  [R_0805]  106.58 7.67 0 bottom
PR503  51.1K_0402_1%  [R_0402]  100.57 7.33 180 bottom
PR504  0_0402_5%  [R_0402]  97.77 7.46 90 bottom
PR505  48.7K_0402_1%  [R_0402]  101.48 7.36 90 bottom
PR506  0_0402_5%  [R0402_0OHM]  98.66 8.37 270 bottom
PR507  0_0402_5%  [R0402_0OHM]  94.65 14.85 270 bottom
PR508  1M_0402_1%  [R_0402]  95.54 13.93 90 bottom
PR509  0_0402_5%  [R0402_0OHM]  98.71 17.52 270 bottom
PR510  1M_0402_1%  [R_0402]  97.5 14.34 90 bottom
PR511  0_0402_5%  [R_0402]  99.6 17.52 270 bottom
PR600  4.7_1206_5%  [R_1206]  251.99 13.58 0 top
PR601  0_0402_5%  [R0402_0OHM]  248.8 18.46 90 bottom
PR602  14K_0402_1%  [R_0402]  251.83 11.27 90 top
PR603  0_0402_5%  [R0402_0OHM]  254.34 13.2 180 bottom
PR604  1M_0402_1%  [R_0402]  253.37 12.26 270 bottom
PR605  20K_0402_1%  [R_0402]  249.74 12.26 270 bottom
PR606  0_0402_5%  [R_0402]  251.6 11.34 90 bottom
PR607  0_0402_5%  [R_0402]  250.66 12.26 270 bottom
PR700  4.7_1206_5%  [R_1206]  67 69.08 180 bottom
PR701  0_0402_5%  [R0402_0OHM]  69.15 70.35 0 top
PR703  100_0402_1%  [R_0402]  66.43 62.42 270 top
PR704  1M_0402_1%  [R_0402]  62.15 60.63 0 top
PR705  0_0402_5%  [R0402_0OHM]  66.63 60.57 180 top
PR706  36.5K_0402_1%  [R_0402]  67.75 63.24 0 top
PR707  0_0402_5%  [R_0402]  65.47 63.36 0 top
PR708  62K_0402_1%  [R_0402]  68.67 62.35 180 top
PR709  0_0402_5%  [R0402_0OHM]  66.38 64.25 180 top
PR710  0_0402_5%  [R0402_0OHM]  66.63 59.68 180 top
PR711  100_0402_1%  [R_0402]  67.75 61.46 0 top
PR712  0_0402_5%  [R0402_0OHM]  191.17 22.88 0 top
PR801  0_0402_5%  [R0402_0OHM]  229.88 43.17 0 top
PR802  4.7_1206_5%  [R_1206]  224.67 42.28 0 top
PR803  0_0402_5%  [R0402_0OHM]  221.75 46.65 90 bottom
PR804  62K_0402_1%  [R_0402]  227.29 37.07 180 bottom
PR805  21.5K_0402_1%  [R_0402]  221.6 39.41 90 bottom
PR806  0_0402_5%  [R0402_0OHM]  227.29 36.19 180 bottom
PR807  1M_0402_1%  [R_0402]  226.37 37.96 0 bottom
PR808  31.6K_0402_1%  [R_0402]  222.49 40.33 270 bottom
PR809  0_0402_5%  [R_0402]  224.27 39.41 90 bottom
PR810  0_0402_5%  [R0402_0OHM]  223.38 40.33 270 bottom
PR811  10K_0402_5%  [R_0402]  229.88 44.06 0 top
PR900  100K_0402_1%  [R_0402]  144.18 109.39 90 bottom
PR901  2.2_0603_5%  [R_0603]  143.11 115.81 90 bottom
PR902  44.2K_0402_1%  [R_0402]  143.29 109.41 90 bottom
PR903  0_0402_5%  [R0402_0OHM]  141.95 109.08 180 bottom
PR904  4.7_1206_5%  [R_1206]  145.48 129.68 90 top
PR905  470K_0402_1%  [R_0402]  138.19 111.12 90 bottom
PR906  36K_0402_1%  [R_0402]  139.79 109.08 180 bottom
PR907  39K_0402_1%  [R_0402]  139.79 110.1 180 bottom
PR908  0_0402_5%  [R0402_0OHM]  144.94 108.73 90 top
PR909  100K_0402_5%  [R_0402]  145.86 108.73 90 top
PR910  169K_0402_1%  [R_0402]  142.96 110.51 90 top
PR911  100_0402_1%  [R_0402]  142.1 111.8 180 top
PR912  0_0402_5%  [R0402_0OHM]  141.18 110.91 0 top
PR913  100K_0402_1%  [R_0402]  143.7 108.14 180 bottom
PR1000  10K_0402_5%  [R_0402]  209.97 117.52 0 bottom
PR1002  4.7_1206_5%  [R_1206]  206.51 116.6 0 top
PR1003  0_0402_5%  [R0402_0OHM]  205.95 121.3 90 bottom
PR1004  100K_0402_1%  [R_0402]  204.38 114.39 0 bottom
PR1007  1M_0402_1%  [R_0402]  210.04 115.28 270 bottom
PR1008  49.9K_0402_1%  [R_0402]  206.21 115.31 270 bottom
PR1009  0_0402_5%  [R_0402]  208.13 114.38 90 bottom
PR1010  0_0402_5%  [R0402_0OHM]  207.23 115.29 270 bottom
PR1011  0_0402_5%  [R0402_0OHM]  210.96 114.37 90 bottom
PR1100  12.1K_0402_1%  [R_0402]  65.54 83.1 90 bottom
PR1101  1_0402_5%  [R_0402]  72.78 80.64 90 bottom
PR1102  0_0402_5%  [R0402_0OHM]  73.67 80.69 90 bottom
PR1103  45.3_0402_1%  [R_0402]  69.1 80.69 90 bottom
PR1104  100_0402_1%  [R_0402]  70.88 80.69 90 bottom
